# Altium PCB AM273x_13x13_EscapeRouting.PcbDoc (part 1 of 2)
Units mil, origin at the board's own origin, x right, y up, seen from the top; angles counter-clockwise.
Board outline 4950 x 3450 mil, 4 copper layers (Top Layer, GND, Power, Bottom Layer), stack 65.634 mil thick; 41 components, 133 nets, 293 pads, 159 vias.
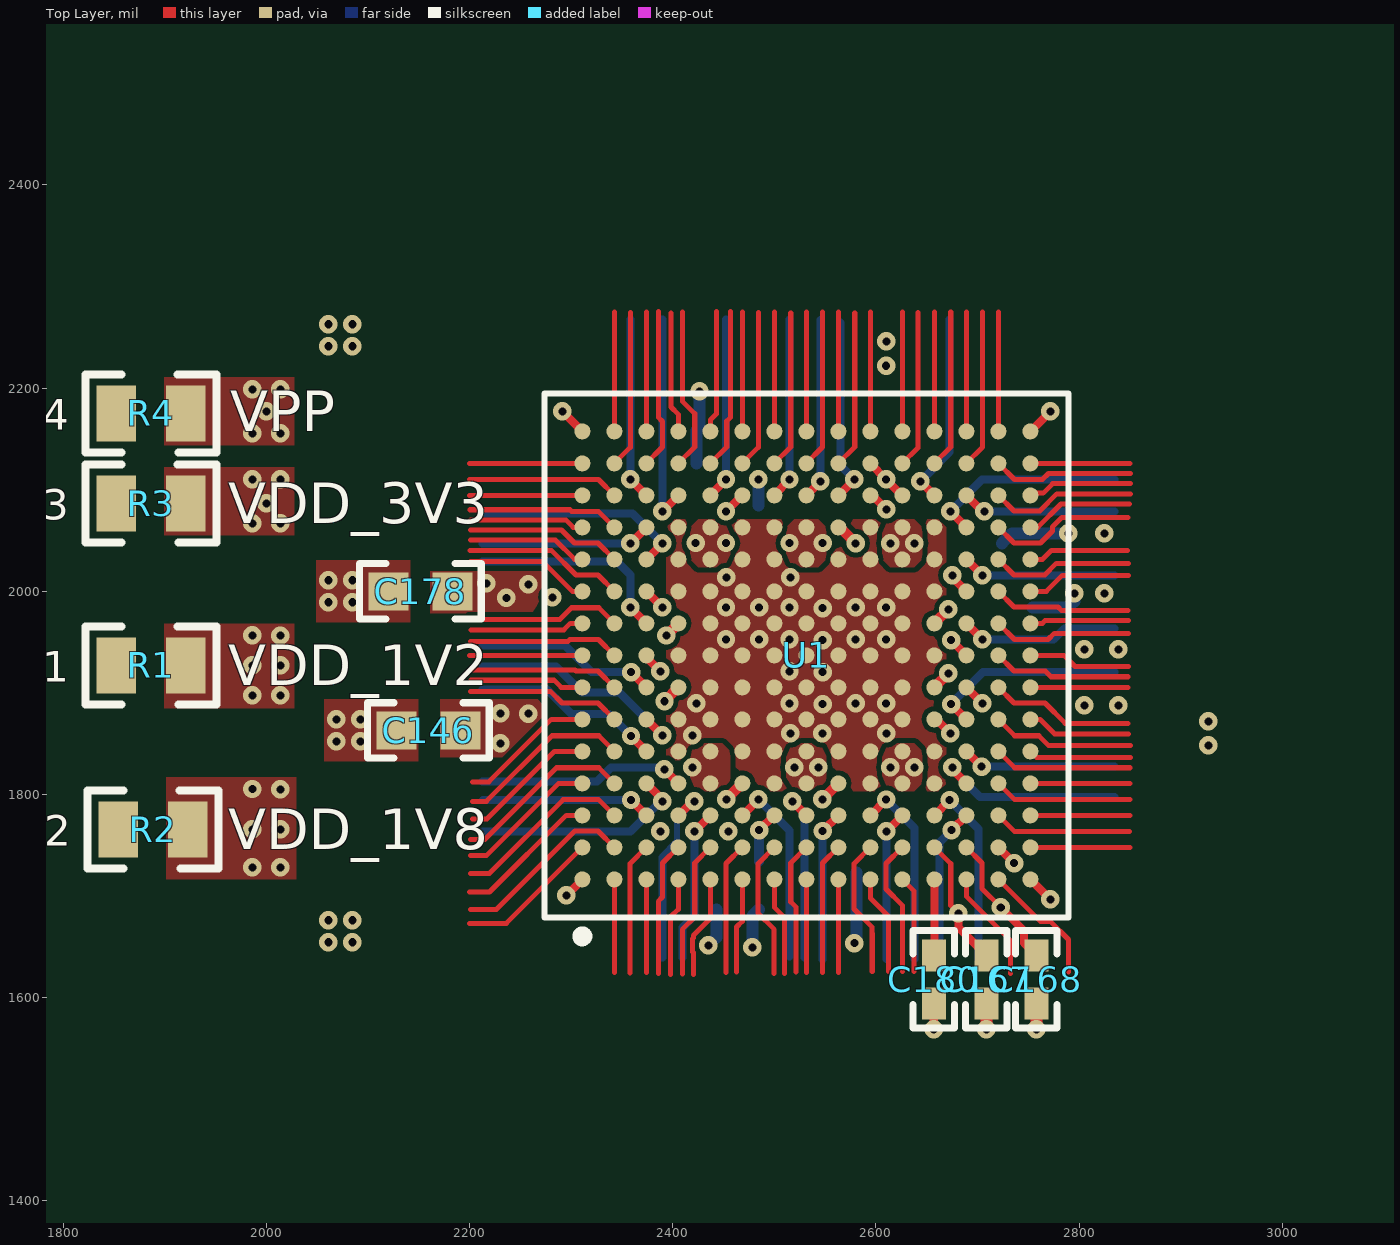
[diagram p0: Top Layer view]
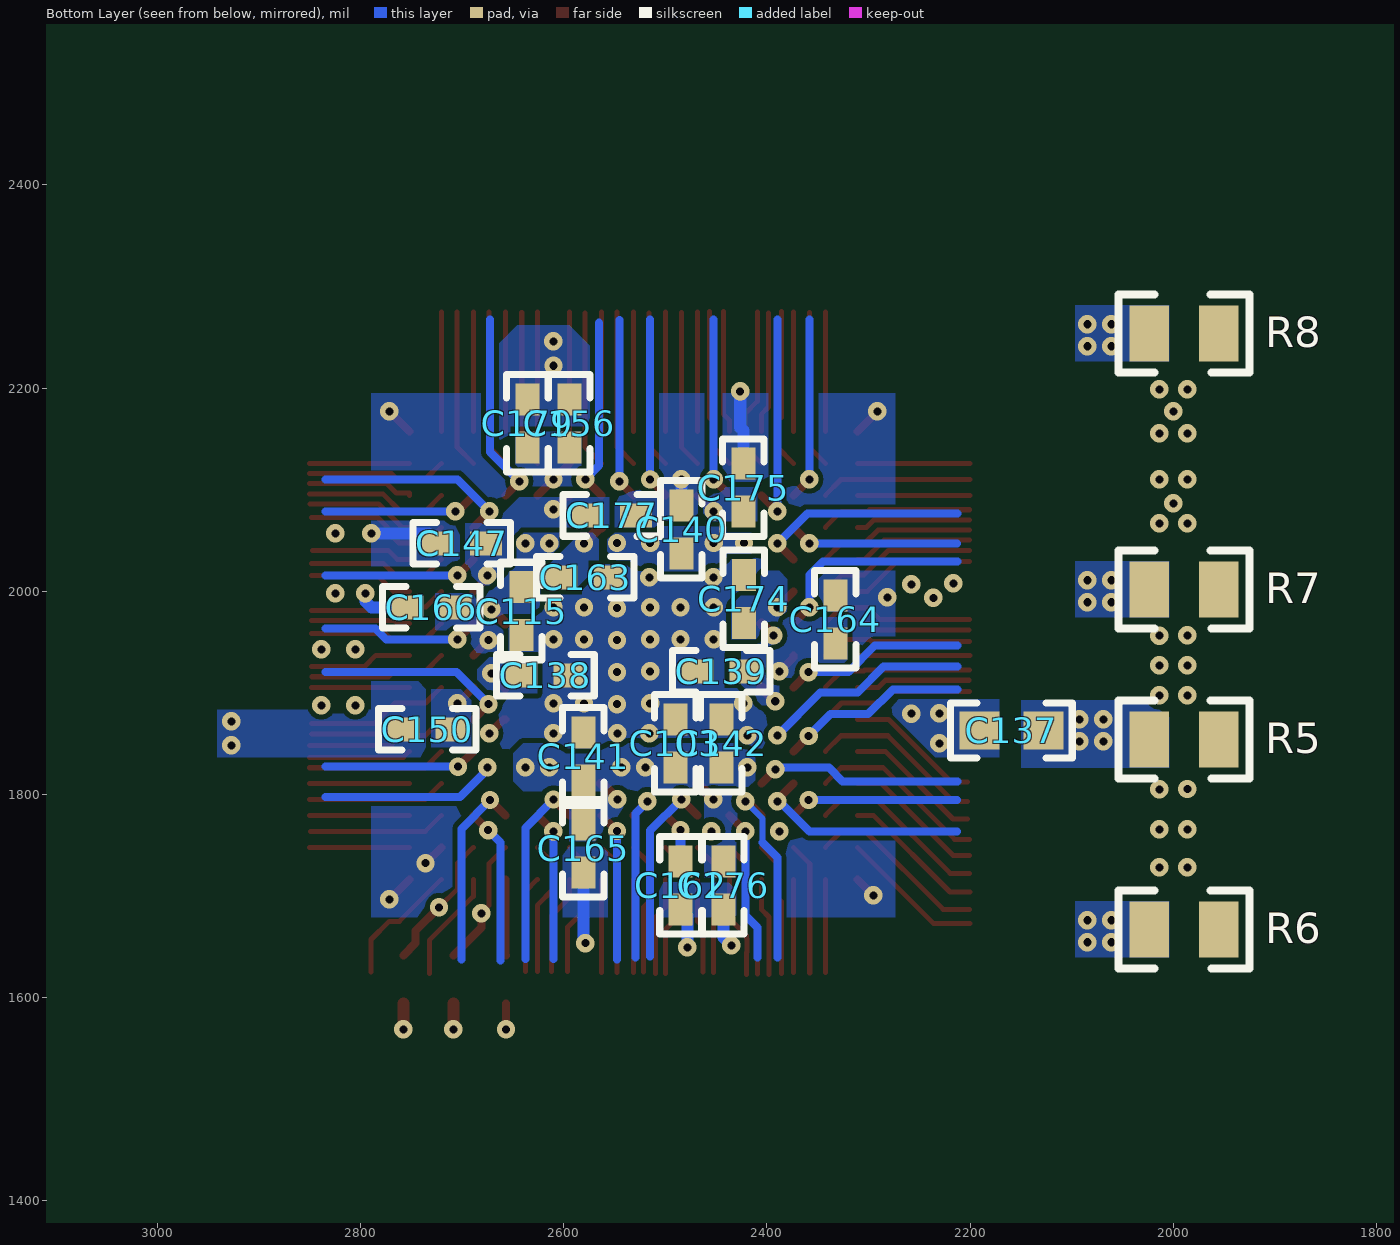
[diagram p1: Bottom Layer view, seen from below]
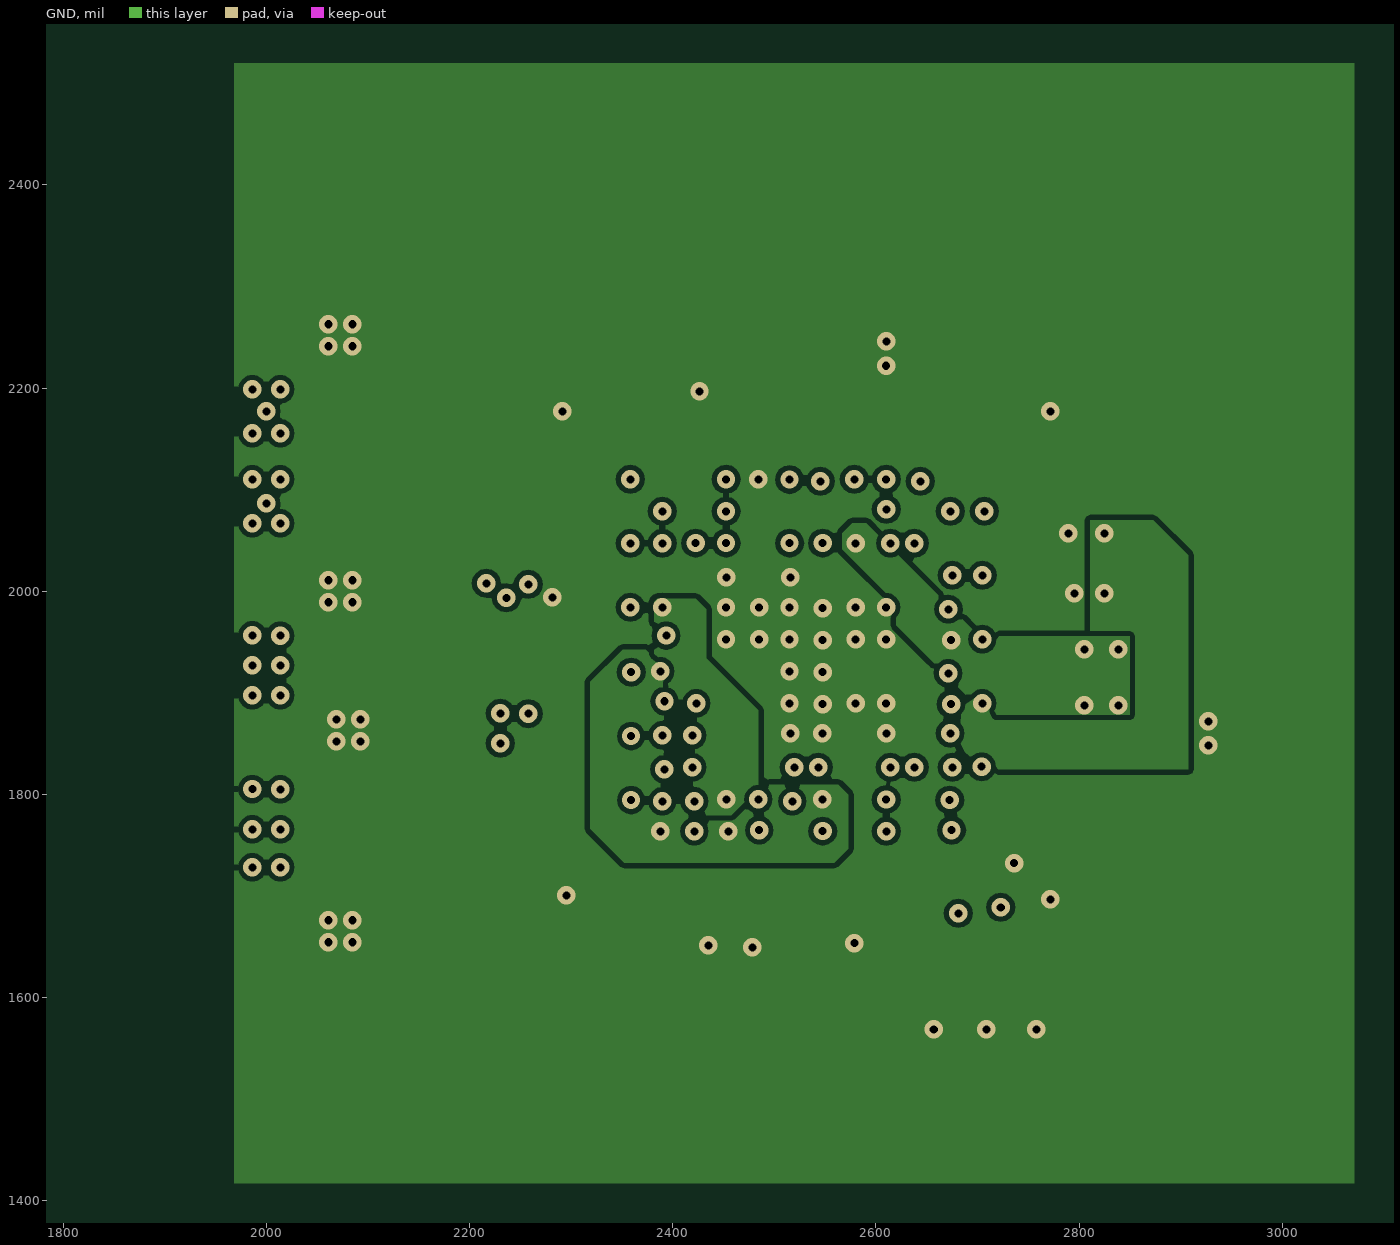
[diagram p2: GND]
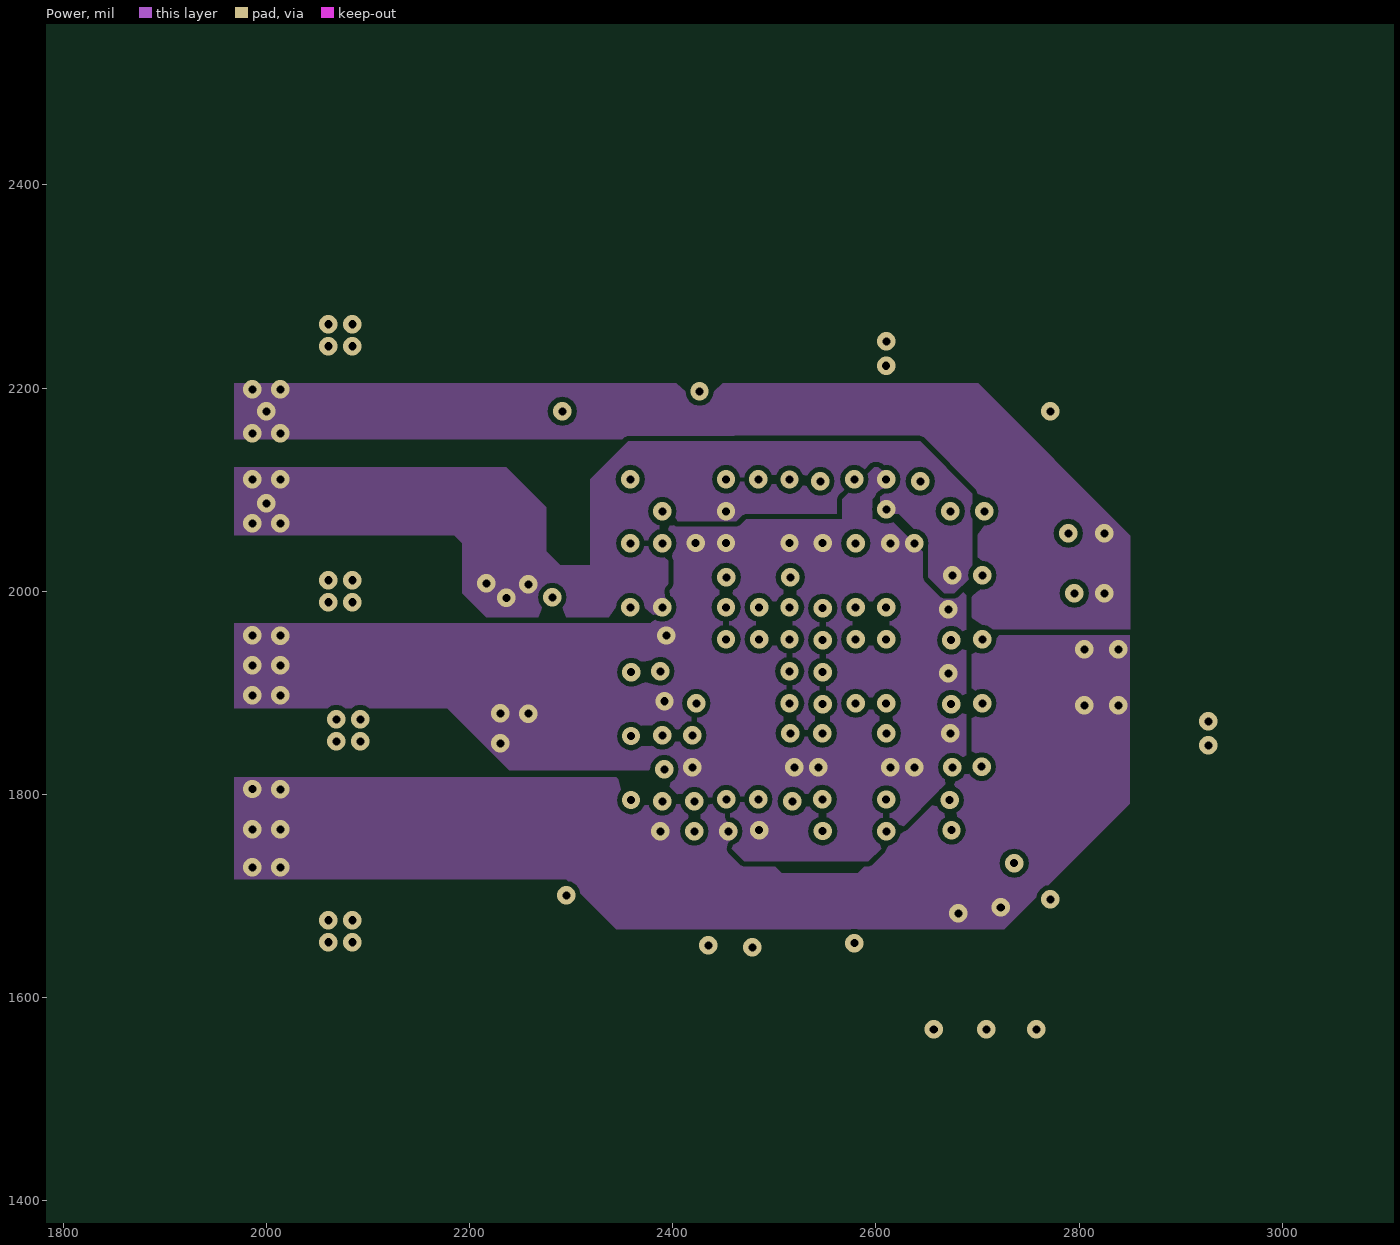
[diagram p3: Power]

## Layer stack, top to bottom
Top Solder: solder mask 0.4, Solder Resist, Dk 3.5
Top Layer: signal copper 1.4
Dielectric 2: core 10, 370HR, Dk 4.2
GND: signal copper 1.417
Dielectric1: prepreg 40, FR-4 High Tg, Dk 4.2
Power: signal copper 1.417
Dielectric 3: core 10, 370HR, Dk 4.2
Bottom Layer: signal copper 1.4
Bottom Solder: solder mask 0.4, Solder Resist, Dk 3.5

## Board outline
0,0 4950,0 4950,3450 0,3450

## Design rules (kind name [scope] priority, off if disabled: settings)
AcuteAngle [All] p1: minimum=4.50000000000000E+0001 checktracksonly=FALSE
AssemblyTestPointUsage [All] p1: valid=2
BoardOutlineClearance BoardOutlineClearance_MountingHoles [OnCopper and InComponentClass('Mounting Holes')] p1: gap=39.37 ignorepadtopadclearanceinfootprint=FALSE
BoardOutlineClearance BoardOutlineClearance_Poly [OnCopper and IsPoly] p2: gap=25 ignorepadtopadclearanceinfootprint=FALSE
BoardOutlineClearance [OnCopper and Not InComponentClass('Logo') and not InComponentClass('FiducialMark') and not InRegion(1000,500,4000,800) and not InPoly] p3: gap=40 ignorepadtopadclearanceinfootprint=FALSE
Clearance Clearance_Keepouts [((IsTrack Or IsArc) And Not InPoly) And IsFree and IsKeepOut vs ((IsTrack Or IsArc) And Not InPoly) And IsFree and IsKeepOut] p1: gap=0 ignorepadtopadclearanceinfootprint=FALSE
Clearance Clearance_Poly [InPolygon] p2: gap=5 ignorepadtopadclearanceinfootprint=TRUE
Clearance Clearance_FiducialMark [IsKeepOut and InComponentClass('FiducialMark') vs IsPad and InComponentClass('FiducialMark')] p3: gap=0 ignorepadtopadclearanceinfootprint=FALSE
Clearance Clearance_Top [OnLayer('Top Layer') vs OnLayer('Top Layer')] p4: gap=5 ignorepadtopadclearanceinfootprint=TRUE
Clearance Clearance_Bottom [OnLayer('Bottom Layer') vs OnLayer('Bottom Layer')] p5: gap=5 ignorepadtopadclearanceinfootprint=TRUE
Clearance [All] p6: gap=4 ignorepadtopadclearanceinfootprint=TRUE
ComponentClearance ComponentClearance_MountingHoles_FiducialMarks [InComponentClass('Mounting Holes') vs InComponentClass('FiducialMark')] p1: gap=50 collisioncheckmode=3 verticalgap=10 showdistances=FALSE
ComponentClearance ComponentClearance_Shunt [InComponentClass('Header') vs InComponentClass('Shunt')] p2: gap=0 collisioncheckmode=3 verticalgap=0 showdistances=FALSE
ComponentClearance ComponentClearance_Logo [InComponentClass('Logo')] p3: gap=30 collisioncheckmode=3 verticalgap=10 showdistances=FALSE
ComponentClearance ComponentClearance_ScrewToNut [(HasFootprint('NY PMS 440 0025 PH')) vs (HasFootprint('Keystone_1902C'))] p4: gap=5 collisioncheckmode=3 verticalgap=10 showdistances=FALSE
ComponentClearance ComponentClearance_MountingHoles [InComponentClass('Mounting Holes')] p5: gap=100 collisioncheckmode=3 verticalgap=100000 showdistances=FALSE
ComponentClearance ComponentClearance_SmallPassives [HasFootprint('0201*') or HasFootprint('0402*') or HasFootprint('0508') or HasFootprint('0603*') or HasFootprint('0612') or HasFootprint('0805*') or HasFootprint('0815*') or HasFootprint('0830*') or HasFootprint('1206*') or HasFootprint('1210*') or HasFootprint('1808*') or HasFootprint('1812*') or HasFootprint('1825*') or HasFootprint('2010*') or HasFootprint('2220*') or HasFootprint('2225*') or HasFootprint('2512*') or HasFootprint('2728*') or HasFootprint('3518*') vs HasFootprint('0201*') or HasFootprint('0402*') or HasFootprint('0508') or HasFootprint('0603*') or HasFootprint('0612') or HasFootprint('0805*') or HasFootprint('0815*') or HasFootprint('0830*') or HasFootprint('1206*') or HasFootprint('1210*') or HasFootprint('1808*') or HasFootprint('1812*') or HasFootprint('1825*') or HasFootprint('2010*') or HasFootprint('2220*') or HasFootprint('2225*') or HasFootprint('2512*') or HasFootprint('2728*') or HasFootprint('3518*')] p6: gap=14.96 collisioncheckmode=3 verticalgap=10 showdistances=FALSE
ComponentClearance ComponentClearance_THtoSMT [IsThruComponent vs IsSMTComponent] p7: gap=30 collisioncheckmode=3 verticalgap=30 showdistances=FALSE
ComponentClearance ComponentClearance_THtoTH [IsThruComponent vs IsThruComponent] p8: gap=20 collisioncheckmode=3 verticalgap=30 showdistances=FALSE
ComponentClearance [All] p9: gap=20 collisioncheckmode=3 verticalgap=10 showdistances=FALSE
DiffPairsRouting [All] p1: maxlimit=100 minlimit=10 mostfreqgap=10 toplayer_minwidth=15 toplayer_maxwidth=15 toplayer_prefwidth=15 midlayer1_minwidth=15 midlayer1_maxwidth=15 midlayer1_prefwidth=15 midlayer2_minwidth=15 midlayer2_maxwidth=15 midlayer2_prefwidth=15 bottomlayer_minwidth=15 bottomlayer_maxwidth=15 bottomlayer_prefwidth=15 maxuncoupledlength=1000
FabricationTestPointUsage TestPointUsage [All] p1: valid=2 allowmultiple=FALSE
FabricationTestpoint Testpoint [All] p1: side=3 testpointundercomponent=TRUE minsize=40 maxsize=100 preferedsize=60 minholesize=0 maxholesize=40 preferedholesize=32 testpointgrid=1 allowsidetop=TRUE allowsidebottom=TRUE usegrid=TRUE gridtolerance=0.01
FanoutControl Fanout_LCC [IsLCC] p1: bgadir=Out bgaviamode=Centered fanoutstyle=Auto fanoutdirection=Alternating viagrid=1 // Fanout_LCC (Default Rule)
FanoutControl Fanout_BGA [IsBGA] p2: bgadir=Out bgaviamode=Centered fanoutstyle=Auto fanoutdirection=Alternating viagrid=1 // Fanout_BGA (Default Rule)
FanoutControl Fanout_Default [All] p4: bgadir=Out bgaviamode=Centered fanoutstyle=Auto fanoutdirection=Alternating viagrid=1 // Fanout_Default (Default Rule)
FanoutControl Fanout_Small [(CompPinCount < 5)] p5: bgadir=Out bgaviamode=Centered fanoutstyle=Auto fanoutdirection=OutThenIn viagrid=1 // Fanout_Small (Default Rule)
HoleSize [All] p1: absolutevalues=TRUE maxlimit=251 minlimit=7.87 maxpercent=80.000 minpercent=20.000
MinimumAnnularRing MinimumAnnularRing_ThermalPadVias [IsVia and InAnyComponent] p1: minimumring=5.91
MinimumAnnularRing [All] p2: minimumring=5
MinimumSolderMaskSliver MinimumSolderMaskSliver_Logo [InComponentClass('Logo') vs InComponentClass('Logo')] p1: minsoldermaskwidth=0.7
MinimumSolderMaskSliver [All] p2: minsoldermaskwidth=3.94
PlaneConnect [All] p1: planeconnectstyle=Relief reliefexpansion=10 reliefentries=4 reliefconductorwidth=10 reliefairgap=10
PolygonConnect [All] p1: connectstyle=Direct reliefconductorwidth=10 reliefentries=4 polygonreliefangle="90 Angle" airgapwidth=10
RoutingVias ThermalPadVias [IsVia and InAnyComponent] p1: holewidth=7.87 width=19.68 viastyle="Through Hole" minholewidth=7.87 minwidth=19.68 maxholewidth=12.99 maxwidth=23.62
RoutingVias [All] p2: holewidth=8 width=18 viastyle="Through Hole" minholewidth=7.87 minwidth=18 maxholewidth=40 maxwidth=65
SilkToBoardRegionClearance [Not ((IsComment or IsDesignator) And (Hide <> 'False')) and not InRegion(1000,500,4000,800)] p1:
SilkToSilkClearance SilkToSilkClearance_Pb-FreeLogo [(HasFootprint('Pb-Free_Overlay_Medium') OR HasFootprint('Pb-Free_Overlay_Small')) vs (HasFootprint('Pb-Free_Overlay_Medium') OR HasFootprint('Pb-Free_Overlay_Small'))] p1: silktosilkclearance=0
SilkToSilkClearance [All] p2: silktosilkclearance=0
SilkToSolderMaskClearance SilkToComponentPadClearance [(IsPad or IsFill or IsRegion) and InAnycomponent] p1: minsilkscreentomaskgap=5 clearancetoexposedcopper=TRUE
SilkToSolderMaskClearance "Silk to Solder Mask Opening" [All] p2: minsilkscreentomaskgap=0 clearancetoexposedcopper=FALSE
SolderMaskExpansion [All] p1: expansion=1.97 istentingtop=FALSE
UnRoutedNet [All] p1: checkbadconnections=TRUE
Width [All] p1: maxlimit=100 minlimit=4 preferedwidth=10 checkconnectedcopper=TRUE
14 further rules are at their usual default settings.

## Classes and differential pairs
component class AM273x_Device: C103 C115 C137 C138 C139 C140 C141 C142 C146 C147 C150 C156 C162 C163 C164 C165 C166 C167 C168 C174 C175 C176 C177 C178 C179 C180 R1 R2 R3 R4 R5 R6 R7 R8 U1
component class Logo: Logo1
component class AM273x_13x13_EscapeRouting_Hardware: Logo1 Logo3 ZZ1 ZZ2 ZZ3 ZZ4
component class AssemblyNote: ZZ1 ZZ2 ZZ3 ZZ4

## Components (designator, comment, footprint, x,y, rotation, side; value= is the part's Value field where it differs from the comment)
C103 "CGA2B3X7R1H103K050BB" 0402 2490.16,1850.39 r270 bottom value=0.01uF
C115 "CGA2B3X7R1H103K050BB" 0402 2641.73,1980.63 r90 bottom value=0.01uF
C137 "GRM188R61C225KAAD" 0603 2159.45,1863.08 r0 bottom value=2.2uF
C138 "GRM155R71A224KE01D" 0402 2618.03,1917.32 r0 bottom value=0.22uF
C139 "GRM155R71A224KE01D" 0402 2444.88,1921.26 r180 bottom value=0.22uF
C140 "GRM155R71A224KE01D" 0402 2484.25,2061.02 r270 bottom value=0.22uF
C141 "GRM155R71A224KE01D" 0402 2580.71,1837.5 r270 bottom value=0.22uF
C142 "GRM155R71A224KE01D" 0402 2444.88,1850.39 r270 bottom value=0.22uF
C146 "GRM188R61C225KAAD" 0603 2159.45,1863.08 r0 top value=2.2uF
C147 "GRM155R71A224KE01D" 0402 2700.29,2047.24 r180 bottom value=0.22uF
C150 "GCM155R71C104KA55D" 0402 2734.25,1864.17 r180 bottom value=0.1uF
C156 "GRM155R71A224KE01D" 0402 2594.49,2165.35 r270 bottom value=0.22uF
C162 "GCM155R71C104KA55D" 0402 2485,1710.63 r90 bottom value=0.1uF
C163 "GRM155R71A224KE01D" 0402 2578.74,2013.78 r0 bottom value=0.22uF
C164 "GRM155R71A224KE01D" 0402 2332.68,1972.44 r270 bottom value=0.22uF
C165 "GRM155R71A224KE01D" 0402 2580.71,1746.98 r90 bottom value=0.22uF
C166 "GRM155R71A224KE01D" 0402 2730.32,1984.25 r180 bottom value=0.22uF
C167 "GRM155R71A224KE01D" 0402 2708.66,1618.11 r90 top value=0.22uF
C168 "GRM155R71A224KE01D" 0402 2757.87,1618.11 r90 top value=0.22uF
C174 "GRM155R71A224KE01D" 0402 2422.74,1992.62 r270 bottom value=0.22uF
C175 "GRM155R71A224KE01D" 0402 2423.23,2102.15 r270 bottom value=0.22uF
C176 "GRM155R71A224KE01D" 0402 2442.91,1710.63 r90 bottom value=0.22uF
C177 "GRM155R71A224KE01D" 0402 2552.7,2074.69 r0 bottom value=0.22uF
C178 "GRM188R61C225KAAD" 0603 2151.57,2000 r0 top value=2.2uF
C179 "GCM155R71C104KA55D" 0402 2635.83,2165.35 r270 bottom value=0.1uF
C180 "CGA2B3X7R1H473K050BB" 0402 2656.89,1618.11 r90 top value=0.047uF
Logo1 "Texas Instruments" TI_Stacked_Overlay_Small 3240,140 r0 top
Logo3 "FCC disclaimer" FCC_disclaimer 2350,3380 r0 top
R1 "5106" 5106 1885.83,1927.17 r0 top value=0
R2 "5106" 5106 1887.8,1765.75 r0 top value=0
R3 "5106" 5106 1885.83,2086.61 r0 top value=0
R4 "5106" 5106 1885.83,2175.2 r0 top value=0
R5 "5106" 5106 1990.16,1854.33 r180 bottom value=0
R6 "5106" 5106 1990.16,1667.32 r180 bottom value=0
R7 "5106" 5106 1990.16,2001.97 r180 bottom value=0
R8 "5106" 5106 1990.16,2253.94 r180 bottom value=0
U1 "AM2732ADRFGQNZNRQ1" NZN0225A-MFG 2531.5,1937.01 r90 top
ZZ1 "This Assembly Note is for PCB labels only" AssemblyNoteLabel 185,3938 r0 top
ZZ2 "These assemblies are ESD sensitive, ESD precautions shall be observed." AssemblyNote 185,3829.11 r0 top
ZZ3 "These assemblies must be clean and free from flux and all contaminants. Use of no clean flux is not acceptable." AssemblyNote 185,3740.56 r0 top
ZZ4 "These assemblies must comply with workmanship standards IPC-A-610 Class 2, unless otherwise specified." AssemblyNote 185,3652 r0 top

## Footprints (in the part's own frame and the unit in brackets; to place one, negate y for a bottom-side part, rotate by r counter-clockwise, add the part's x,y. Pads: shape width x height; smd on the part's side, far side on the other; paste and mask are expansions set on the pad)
0402 [mm] "0402 from SM-752 data"
  rect 0.8x0.6 smd: 1(-0.6,0) 2(0.6,0)
  silkscreen extent -1.22,-0.52 1.22,0.52, body extent -0.55,-0.3 0.55,0.3, height 0.6
0603 [mm] "0603 from SM-752 data"
  rect 1x0.95 smd: 1(-0.8,0) 2(0.8,0)
  silkscreen extent -1.52,-0.69 1.52,0.69, body extent -0.87,-0.47 0.87,0.47, height 1
5106 [mm] "Keystone"
  rect 0.99x1.4 smd: 1(-0.85,0) 2(0.88,0)
  silkscreen extent -1.63,-0.97 1.65,0.97, body extent -1.06,-0.69 1.06,0.69, height 0.84
AssemblyNote [mil] "Assembly Note"
AssemblyNoteLabel [mil] "Assembly Note for PCB Labels"
FCC_disclaimer [mil]
NZN0225A-MFG [mm]
  round 0.4 smd paste+0 mask-1000: A1(-5.6,5.6) A2(-4.8,5.6) A3(-4,5.6) A4(-3.2,5.6) A5(-2.4,5.6) A6(-1.6,5.6) A7(-0.8,5.6) A8(0,5.6) A9(0.8,5.6) A10(1.6,5.6) A11(2.4,5.6) A12(3.2,5.6) A13(4,5.6) A14(4.8,5.6) A15(5.6,5.6) B1(-5.6,4.8) B2(-4.8,4.8) B3(-4,4.8) B4(-3.2,4.8) B5(-2.4,4.8) B6(-1.6,4.8) B7(-0.8,4.8) B8(0,4.8) B9(0.8,4.8) B10(1.6,4.8) B11(2.4,4.8) B12(3.2,4.8) B13(4,4.8) B14(4.8,4.8) B15(5.6,4.8) C1(-5.6,4) C2(-4.8,4) C3(-4,4) C4(-3.2,4) C5(-2.4,4) C6(-1.6,4) C7(-0.8,4) C8(0,4) C9(0.8,4) C10(1.6,4) C11(2.4,4) C12(3.2,4) C13(4,4) C14(4.8,4) C15(5.6,4) D1(-5.6,3.2) D2(-4.8,3.2) D3(-4,3.2) D4(-3.2,3.2) D5(-2.4,3.2) D6(-1.6,3.2) D7(-0.8,3.2) D8(0,3.2) D9(0.8,3.2) D10(1.6,3.2) D11(2.4,3.2) D12(3.2,3.2) D13(4,3.2) D14(4.8,3.2) D15(5.6,3.2) E1(-5.6,2.4) E2(-4.8,2.4) E3(-4,2.4) E4(-3.2,2.4) E5(-2.4,2.4) E6(-1.6,2.4) E7(-0.8,2.4) E8(0,2.4) E9(0.8,2.4) E10(1.6,2.4) E11(2.4,2.4) E12(3.2,2.4) E13(4,2.4) E14(4.8,2.4) E15(5.6,2.4) F1(-5.6,1.6) F2(-4.8,1.6) F3(-4,1.6) F4(-3.2,1.6) F5(-2.4,1.6) F6(-1.6,1.6) F7(-0.8,1.6) F8(0,1.6) F9(0.8,1.6) F10(1.6,1.6) F11(2.4,1.6) F12(3.2,1.6) F13(4,1.6) F14(4.8,1.6) F15(5.6,1.6) G1(-5.6,0.8) G2(-4.8,0.8) G3(-4,0.8) G4(-3.2,0.8) G5(-2.4,0.8) G6(-1.6,0.8) G7(-0.8,0.8) G8(0,0.8) G9(0.8,0.8) G10(1.6,0.8) G11(2.4,0.8) G12(3.2,0.8) G13(4,0.8) G14(4.8,0.8) G15(5.6,0.8) H1(-5.6,0) H2(-4.8,0) H3(-4,0) H4(-3.2,0) H5(-2.4,0) H6(-1.6,0) H7(-0.8,0) H8(0,0) H9(0.8,0) H10(1.6,0) H11(2.4,0) H12(3.2,0) H13(4,0) H14(4.8,0) H15(5.6,0) J1(-5.6,-0.8) J2(-4.8,-0.8) J3(-4,-0.8) J4(-3.2,-0.8) J5(-2.4,-0.8) J6(-1.6,-0.8) J7(-0.8,-0.8) J8(0,-0.8) J9(0.8,-0.8) J10(1.6,-0.8) J11(2.4,-0.8) J12(3.2,-0.8) J13(4,-0.8) J14(4.8,-0.8) J15(5.6,-0.8) K1(-5.6,-1.6) K2(-4.8,-1.6) K3(-4,-1.6) K4(-3.2,-1.6) K5(-2.4,-1.6) K6(-1.6,-1.6) K7(-0.8,-1.6) K8(0,-1.6) K9(0.8,-1.6) K10(1.6,-1.6) K11(2.4,-1.6) K12(3.2,-1.6) K13(4,-1.6) K14(4.8,-1.6) K15(5.6,-1.6) L1(-5.6,-2.4) L2(-4.8,-2.4) L3(-4,-2.4) L4(-3.2,-2.4) L5(-2.4,-2.4) L6(-1.6,-2.4) L7(-0.8,-2.4) L8(0,-2.4) L9(0.8,-2.4) L10(1.6,-2.4) L11(2.4,-2.4) L12(3.2,-2.4) L13(4,-2.4) L14(4.8,-2.4) L15(5.6,-2.4) M1(-5.6,-3.2) M2(-4.8,-3.2) M3(-4,-3.2) M4(-3.2,-3.2) M5(-2.4,-3.2) M6(-1.6,-3.2) M7(-0.8,-3.2) M8(0,-3.2) M9(0.8,-3.2) M10(1.6,-3.2) M11(2.4,-3.2) M12(3.2,-3.2) M13(4,-3.2) M14(4.8,-3.2) M15(5.6,-3.2) N1(-5.6,-4) N2(-4.8,-4) N3(-4,-4) N4(-3.2,-4) N5(-2.4,-4) N6(-1.6,-4) N7(-0.8,-4) N8(0,-4) N9(0.8,-4) N10(1.6,-4) N11(2.4,-4) N12(3.2,-4) N13(4,-4) N14(4.8,-4) N15(5.6,-4) P1(-5.6,-4.8) P2(-4.8,-4.8) P3(-4,-4.8) P4(-3.2,-4.8) P5(-2.4,-4.8) P6(-1.6,-4.8) P7(-0.8,-4.8) P8(0,-4.8) P9(0.8,-4.8) P10(1.6,-4.8) P11(2.4,-4.8) P12(3.2,-4.8) P13(4,-4.8) P14(4.8,-4.8) P15(5.6,-4.8) R1(-5.6,-5.6) R2(-4.8,-5.6) R3(-4,-5.6) R4(-3.2,-5.6) R5(-2.4,-5.6) R6(-1.6,-5.6) R7(-0.8,-5.6) R8(0,-5.6) R9(0.8,-5.6) R10(1.6,-5.6) R11(2.4,-5.6) R12(3.2,-5.6) R13(4,-5.6) R14(4.8,-5.6) R15(5.6,-5.6)
  silkscreen extent -7.15,-6.55 6.55,6.55, body extent -7.05,-7.05 7.05,7.05, height 0.25
TI_Stacked_Overlay_Small [mil]
  silkscreen extent -418,-98 418,98

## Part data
C103 C115: library part CMP-0006324-2, "CAP, CERM, 0.01 uF, 50 V, +/- 10%, X7R, AEC-Q200 Grade 1, 0402", Cap_Case=0402, Manufacturer=TDK, Supplier Part Number 1=445-6893-1-ND, TempCo=X7R, Tolerance_%=10%, Value1="0.333065 ohm", Value2=50V, ValueDisplayed=0.01uF
C137 C146 C178: library part CMP-0007338-4, "CAP, CERM, 2.2 uF, 16 V, +/- 10%, X5R, 0603", Cap_Case=0603, Manufacturer=MuRata, TempCo=X5R, Tolerance_%=10%, Value1=Unknown, Value2=16V, ValueDisplayed=2.2uF
C138 C139 C140 C141 C142 C147 C156 C163 C164 C165 C166 C167 C168 C174 C175 C176 C177: library part CMP-0006630-1, "CAP, CERM, 0.22 uF, 10 V, +/- 10%, X7R, 0402", Cap_Case=0402, Manufacturer=MuRata, Supplier Part Number 1=490-12706-1-ND, TempCo=X7R, Tolerance_%=10%, Value1=Unknown, Value2=10V, ValueDisplayed=0.22uF
C150 C162 C179: library part CMP-0006351-2, "CAP, CERM, 0.1 uF, 16 V, +/- 10%, X7R, 0402", Cap_Case=0402, Manufacturer=MuRata, Supplier Part Number 1=490-4759-2-ND, TempCo=X7R, Tolerance_%=10%, Value1=Unknown, Value2=16V, ValueDisplayed=0.1uF
C180: library part CMP-0006330-2, "CAP, CERM, 0.047 uF, 50 V, +/- 10%, X7R, AEC-Q200 Grade 1, 0402", Cap_Case=0402, Manufacturer=TDK, Supplier Part Number 1=445-6897-1-ND, TempCo=X7R, Tolerance_%=10%, Value1="0.06407 ohm", Value2=50V, ValueDisplayed=0.047uF
Logo1: library part CMP-0074838-1, "Texas Instrument Corporate Signature"
Logo3: library part CMP-0074847-1, "FCC_disclaimer"
R1 R2 R3 R4 R5 R6 R7 R8: library part CMP-0020833-2, "RES, 0, 1%, 0.5 W, 0805", Manufacturer=Keystone, Power_W=500mW, Supplier Part Number 1=36-5106CT-ND, TempCo=ppm/C, Tolerance_%=1%, Value2=0.5W, Value_Code=0
U1: library part CMP-0093973-1, "TPR12", Manufacturer="Texas Instruments", Operating Temperature Range=to
ZZ1: library part CMP-0003616-3
ZZ2: library part CMP-0077236-1
ZZ3: library part CMP-0077237-1
ZZ4: library part CMP-0077238-1

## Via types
v1: diameter 18, hole 8, Top Layer to Bottom Layer, tented both sides, 135 vias
v2: diameter 18, hole 8, Top Layer to Bottom Layer, 24 vias

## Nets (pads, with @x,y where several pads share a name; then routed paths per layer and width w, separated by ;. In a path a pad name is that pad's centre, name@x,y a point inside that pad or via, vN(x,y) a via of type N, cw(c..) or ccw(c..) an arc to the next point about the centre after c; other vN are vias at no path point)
A2: U1.A2 | length 142
  Top Layer w5: 2200,1673.23 2236.22,1673.23 U1.A2@2311.02,1748.03
A3: U1.A3 | length 142.3
  Top Layer w5: 2200,1703.98 2219.72,1703.98 2295.28,1779.53 U1.A3@2311.02,1779.53
A4: U1.A4 | length 139.6
  Top Layer w5: 2200.79,1740.16 2216.82,1740.16 2287.69,1811.02 U1.A4@2311.02,1811.02
A5: U1.A5 | length 135.9
  Top Layer w5: 2202.76,1775.91 2216.96,1775.91 2283.57,1842.52 U1.A5@2311.02,1842.52
A6: U1.A6 | length 133.7
  Top Layer w5: 2202.76,1812.5 2218.96,1812.5 2280.48,1874.02 U1.A6@2311.02,1874.02
A7: U1.A7 | length 112.6
  Top Layer w5: 2201.3,1912.5 2283.24,1912.5 2290.23,1905.51 U1.A7@2311.02,1905.51
A8: U1.A8 | length 111
  Top Layer w5: 2200,1937.01 U1.A8@2311.02,1937.01
A9: U1.A9 | length 112.4
  Top Layer w5: 2201.3,1962.08 2292.79,1962.08 2299.21,1968.5 U1.A9@2311.02,1968.5
A10: U1.A10 | length 122.5
  Top Layer w5: 2200.79,2029.53 2271.65,2029.53 2301.18,2000 U1.A10@2311.02,2000
A11: U1.A11 | length 118
  Top Layer w5: 2200.79,2050.35 2284.57,2050.35 2303.42,2031.5 U1.A11@2311.02,2031.5
A12: U1.A12 | length 113.3
  Top Layer w5: 2200.79,2070.35 2294.67,2070.35 2302.04,2062.99 U1.A12@2311.02,2062.99
A13: U1.A13 | length 111
  Top Layer w5: 2200,2094.49 U1.A13@2311.02,2094.49
A14: U1.A14 | length 111
  Top Layer w5: 2200,2125.98 U1.A14@2311.02,2125.98
B1: U1.B1 | length 91.5
  Top Layer w5: 2342.52,1625 U1.B1@2342.52,1716.54
B2: U1.B2 | length 180.4
  Top Layer w5: 2200.79,1687.01 2226.48,1687.01 2303.63,1764.15 2326.4,1764.15 U1.B2@2342.52,1748.03
B3: U1.B3 | length 178.2
  Top Layer w5: 2200.79,1722.44 2219.55,1722.44 2292.11,1795 2327.05,1795 U1.B3@2342.52,1779.53
B4: U1.B4 | length 177.3
  Top Layer w5: 2200.79,1755.91 2215.17,1755.91 2285.66,1826.4 2327.15,1826.4 U1.B4@2342.52,1811.02
B5: U1.B5 | length 172.9
  Top Layer w5: 2202.76,1793.31 2216.54,1793.31 2281.12,1857.89 2327.15,1857.89 U1.B5@2342.52,1842.52
B6: U1.B6 | length 153.1
  Top Layer w5: 2200.79,1901.57 2279.53,1901.57 2291.1,1890 2326.54,1890 U1.B6@2342.52,1874.02
B7: U1.B7 | length 149.1
  Top Layer w5: 2200.47,1922.5 2303.79,1922.5 2304.66,1921.63 2326.4,1921.63 U1.B7@2342.52,1905.51
B8: U1.B8 | length 148.9
  Top Layer w5: 2200.79,1950.79 2297.04,1950.79 2298.75,1952.5 2327.03,1952.5 U1.B8@2342.52,1937.01
B9: U1.B9 | length 152.8
  Top Layer w5: 2200.79,1972.44 2288.93,1972.44 2300.36,1983.88 2327.15,1983.88 U1.B9@2342.52,1968.5
B10: U1.B10 | length 158.8
  Top Layer w5: 2200.47,2040.35 2280.42,2040.35 2304.66,2016.12 2326.4,2016.12 U1.B10@2342.52,2000
B11: U1.B11 | length 153.7
  Top Layer w5: 2200.79,2060.35 2290.53,2060.35 2303.39,2047.5 2326.52,2047.5 U1.B11@2342.52,2031.5
B12: U1.B12 | length 149.2
  Top Layer w5: 2200.47,2080.35 2298.82,2080.35 2300.43,2078.74 2326.77,2078.74 U1.B12@2342.52,2062.99
B13: U1.B13 | length 148.9
  Top Layer w5: 2200,2110 2327.01,2110 U1.B13@2342.52,2094.49
B14: U1.B14 | length 154.8
  Top Layer w5: U1.B14@2342.52,2125.98 2358.27,2141.73 2358.27,2274.23
B15: U1.B15 | length 117.5
  Top Layer w5: U1.B15@2342.52,2157.48 2342.52,2274.98
C1: U1.C1 | length 91.5
  Top Layer w5: 2374.02,1625 U1.C1@2374.02,1716.54
C2: U1.C2 | length 130.3
  Top Layer w5: 2357.89,1624.41 2357.89,1731.91 U1.C2@2374.02,1748.03
C3: U1.C3 | length 167.2
  Top Layer w8: v1(2359,1794.55) U1.C3@2374.02,1779.53
  Bottom Layer w8: 2213.05,1794.55 v1(2359,1794.55)
C4: U1.C4 | length 213.2
  Top Layer w8: U1.C4@2374.02,1811.02 2389.76,1795.28 v1(2389.76,1793.31)
  Bottom Layer w8: 2213.05,1763.78 2358.27,1763.78 2387.8,1793.31 v1(2389.76,1793.31)
C5: U1.C5 | length 186.7
  Top Layer w8: v1(2359,1857.54) U1.C5@2374.02,1842.52
  Bottom Layer w8: 2212.6,1903.54 2276.12,1903.54 2300.49,1879.17 2337.37,1879.17 v1(2359,1857.54)
C6: U1.C6 | length 227.5
  Top Layer w8: U1.C6@2374.02,1874.02 v1(2389.76,1858.27)
  Bottom Layer w8: 2212.6,1925.95 2285.18,1925.95 2310.65,1900.49 2347.54,1900.49 v1(2389.76,1858.27)
C7: U1.C7 | length 178.4
  Top Layer w8: v1(2359.04,1920.49) U1.C7@2374.02,1905.51
  Bottom Layer w8: 2212.64,1946.53 2293.88,1946.53 2319.91,1920.49 v1(2359.04,1920.49)
C9: U1.C9 | length 207.4
  Top Layer w8: v1(2358.27,1984.25) U1.C9@2374.02,1968.5
  Bottom Layer w6: v1@2356.3,1984.25 v1(2358.27,1984.25)
  Bottom Layer w8: 2212.6,2029.53 2344.98,2029.53 2358.27,2016.24 v1(2358.27,1984.25)
C11: U1.C11 | length 211.6
  Top Layer w8: U1.C11@2374.02,2031.5 v1(2389.76,2047.24)
  Bottom Layer w8: 2212.64,2076.77 2360.24,2076.77 v1(2389.76,2047.24)
C12: U1.C12 | length 167.7
  Top Layer w8: v1(2358.27,2047.24) U1.C12@2374.02,2062.99
  Bottom Layer w8: 2212.85,2047.24 v1(2358.27,2047.24)
C13: U1.C13 | length 179.8
  Top Layer w8: v1(2358.27,2110.24) U1.C13@2374.02,2094.49
  Bottom Layer w8: v1(2358.27,2110.24) 2358.27,2267.72
C14: U1.C14 | length 158
  Top Layer w5: U1.C14@2374.02,2125.98 2390,2141.97 2390,2167.09 2385.83,2171.26 2385.83,2275.59
C15: U1.C15 | length 117.5
  Top Layer w5: U1.C15@2374.02,2157.48 2374.02,2274.98
D1: U1.D1 | length 96.6
  Top Layer w5: 2397.89,1623.05 2397.89,1679.38 2405.51,1687.01 U1.D1@2405.51,1716.54
D2: U1.D2 | length 132.2
  Top Layer w5: 2385.83,1624.02 2385.83,1694.88 2390,1699.06 2390,1732.52 U1.D2@2405.51,1748.03
D3: U1.D3 | length 188
  Top Layer w8: U1.D3@2405.51,1779.53 2419.29,1793.31 v1(2421.26,1793.31)
  Bottom Layer w6: 2404.3,1752.72 2404.3,1776.34 v1(2421.26,1793.31)
  Bottom Layer w8: 2389.76,1639.76 2389.76,1738.19 2404.3,1752.72
D4: U1.D4 | length 204.9
  Top Layer w8: v1@2390,1826.54 U1.D4@2405.51,1811.02
  Bottom Layer w8: 2212.6,1812.99 2325.51,1812.99 2339.05,1826.54 v1@2390,1826.54
  other v1: 2391.73,1824.8
D13: U1.D13 | length 211
  Top Layer w8: v1(2389.76,2078.74) U1.D13@2405.51,2094.49
  Bottom Layer w8: v1(2389.76,2078.74) 2389.76,2267.48
D14: U1.D14 | length 160.7
  Top Layer w5: U1.D14@2405.51,2125.98 2421.63,2142.11 2421.63,2174.82 2409.45,2187.01 2409.45,2274.98
D15: U1.D15 | length 119.2
  Top Layer w5: 2398.37,2273.75 2398.37,2181.35 2405.51,2174.21 U1.D15@2405.51,2157.48
E1: U1.E1 | length 101
  Top Layer w5: 2420.25,1623.05 2420.25,1644.44 2419.54,1645.15 2419.54,1658 2420.25,1658.71 2420.25,1661.23 2437.01,1677.98 U1.E1@2437.01,1716.54
E2: U1.E2 | length 136.3
  Top Layer w5: 2409.45,1623.19 2409.45,1667.32 2421.63,1679.51 2421.63,1732.66 U1.E2@2437.01,1748.03
E3: U1.E3 | length 151.2
  Top Layer w8: v1(2421.26,1763.78) U1.E3@2437.01,1779.53
  Bottom Layer w8: 2409.45,1639.76 2409.45,1669.29 2421.26,1681.1 v1(2421.26,1763.78)
E13: U1.E13 | length 179.6
  Top Layer w8: U1.E13@2437.01,2094.49 2437.01,2094.74 v1(2452.5,2110.24)
  Bottom Layer w8: v1(2452.5,2110.24) 2452.5,2267.72
E14: U1.E14 | length 157.8
  Top Layer w5: U1.E14@2437.01,2125.98 2453.13,2142.11 2453.13,2167.41 2456.69,2170.97 2456.69,2275.59
E15: U1.E15 | length 120.6
  Top Layer w5: U1.E15@2437.01,2157.48 2437.01,2168.65 2442.91,2174.56 2442.91,2275.59
F1: U1.F1 | length 93.6
  Top Layer w5: 2462.85,1625.25 2462.85,1669.56 2468.5,1675.22 U1.F1@2468.5,1716.54
F2: U1.F2 | length 129.7
  Top Layer w5: 2452.5,1625 2452.5,1732.03 U1.F2@2468.5,1748.03
F3: U1.F3 | length 189.8
  Top Layer w8: U1.F3@2468.5,1779.53 v1(2484.25,1795.27)
  Bottom Layer w8: v1(2484.25,1795.27) 2515,1764.52 2515,1640.51
F14: U1.F14 | length 155.2
  Top Layer w5: U1.F14@2468.5,2125.98 2484.25,2141.73 2484.25,2274.63
F15: U1.F15 | length 117.5
  Top Layer w5: U1.F15@2468.5,2157.48 2468.5,2275
G1: U1.G1 | length 96.6
  Top Layer w5: U1.G1@2500,1716.54 2500,1688.98 2509.84,1679.13 2509.84,1624.02
G2: U1.G2 | length 137.3
  Top Layer w5: 2499.84,1624.02 2499.84,1667.32 2483.88,1683.29 2483.88,1731.91 U1.G2@2500,1748.03
G13: U1.G13 | length 179.4
  Top Layer w8: U1.G13@2500,2094.49 2500,2095 v1(2515,2110)
  Bottom Layer w8: v1(2515,2110) 2515,2267.72
G14: U1.G14 | length 154.7
  Top Layer w5: U1.G14@2500,2125.98 2516.12,2142.11 2516.12,2274
G15: U1.G15 | length 117.5
  Top Layer w5: U1.G15@2500,2157.48 2500,2274.98
GND: C103.1 C115.1 C137.1 C138.1 C139.1 C140.1 C141.1 C142.1 C146.1 C147.1 C150.1 C156.1 C162.1 C163.1 C164.1 C165.1 C166.1 C167.1 C168.1 C174.1 C175.1 C176.1 C177.1 C178.1 C179.1 C180.1 R5.1 R6.1 R7.1 R8.1 U1.A1 U1.A15 U1.D5 U1.D6 U1.D8 U1.D10 U1.D11 U1.D12 U1.E6 U1.E7 U1.E8 U1.E9 U1.E10 U1.F5 U1.F6 U1.F7 U1.F8 U1.F9 U1.F10 U1.F11 U1.F12 U1.G4 U1.G5 U1.G6 U1.G7 U1.G8 U1.G9 U1.G10 U1.G11 U1.G12 U1.H6 U1.H7 U1.H8 U1.H9 U1.H10 U1.J5 U1.J6 U1.J7 U1.J8 U1.J9 U1.J10 U1.J11 U1.K4 U1.K5 U1.K6 U1.K7 U1.K8 U1.K9 U1.K10 U1.K11 U1.K12 U1.L6 U1.L7 U1.L8 U1.L9 U1.L10 U1.M4 U1.M5 U1.M8 U1.M10 U1.M11 U1.M12 U1.P2 U1.R1 U1.R15 | length 577.3
  Top Layer w8: v1(2291.34,2177.17) U1.A15@2311.02,2157.48 ; v1(2295.28,1700.79) U1.A1@2311.02,1716.54 ; v1(2656.89,1568.9) C180.1@2656.89,1594.49 ; U1.P2@2720.47,1748.03 v1(2735.98,1732.52) ; U1.R1@2751.97,1716.54 v1(2771.65,1696.85) ; U1.R15@2751.97,2157.48 v1(2771.65,2177.17)
  Top Layer w12: v2(2708.66,1568.9) C167.1@2708.66,1594.49 ; v2(2757.87,1568.9) C168.1@2757.87,1594.49
  Power w8: v1@2767.25,1696.85 v1(2771.65,1696.85)
  Bottom Layer w12: C175.1@2423.23,2125.77 2423.23,2158.28 2426.37,2161.42 v1(2426.37,2196.85) ; v1(2435.04,1651.57) 2442.91,1659.45 C176.1@2442.91,1687.01 ; v1(2478.35,1649.61) 2478.35,1680.35 C162.1@2485,1687.01 ; C140.1@2484.25,2084.65 v1(2484.25,2110.24) ; v1(2578.74,1653.74) 2580.71,1655.71 C165.1@2580.71,1723.36 ; C147.1@2723.92,2047.24 2733.76,2057.09 v1(2789.37,2057.09) ; C166.1@2753.94,1984.25 2789.37,1984.25 2795.28,1990.16 v1(2795.28,1998.03)
  other v1: 2061.02,1654.64 2084.65,1654.64 2061.02,1676.29 2084.65,1676.29 2927.17,1848.43 2068.9,1852.36 2092.52,1852.36 2419.29,1858.27 2515.75,1860.24 2547.24,1860.24 2610.24,1860.24 2927.17,1872.05 2068.9,1874.02 2092.52,1874.02 2547.5,1889 2423.23,1889.76 2515,1889.76 2580,1889.76 2610,1889.76 2547.5,1920.49 2515,1921.26 2547.5,1951.99 2452.5,1952.76 2485,1952.76 2515,1952.76 2580,1952.76 2610,1952.76 2547.5,1983.48 2452.5,1984.25 2485,1984.25 2515,1984.25 2580,1984.25 2610,1984.25 2061.02,1989.28 2084.65,1989.28 2281.5,1994.09 2061.02,2010.94 2084.65,2010.94 2452.76,2013.78 2515.75,2013.78 2610,2222.09 2061.02,2241.25 2084.65,2241.25 2610.24,2246.06 2061.02,2262.91 2084.65,2262.91
H1: U1.H1 | length 91.5
  Top Layer w5: 2531.5,1625 U1.H1@2531.5,1716.54
H2: U1.H2 | length 131.3
  Top Layer w5: 2521.5,1625.29 2521.5,1689.13 2516.12,1694.51 2516.12,1732.66 U1.H2@2531.5,1748.03
H3: U1.H3 | length 177.9
  Top Layer w8: v1(2517.72,1793.31) U1.H3@2531.5,1779.53
  Bottom Layer w8: v1(2517.72,1793.31) 2529.53,1781.5 2529.53,1639.76
H13: U1.H13 | length 181.2
  Top Layer w8: U1.H13@2531.5,2094.49 v1(2545.28,2108.27) v1@2547.24,2110.23
  Bottom Layer w8: v1(2545.28,2108.27) 2545.28,2267.22
H14: U1.H14 | length 155.6
  Top Layer w5: U1.H14@2531.5,2125.98 2547.5,2141.99 2547.5,2274.98
H15: U1.H15 | length 117.5
  Top Layer w5: U1.H15@2531.5,2157.48 2531.5,2274.98
J1: U1.J1 | length 91.5
  Top Layer w5: 2562.99,1625 U1.J1@2562.99,1716.54
J2: U1.J2 | length 129.4
  Top Layer w5: 2547.5,1625 2547.5,1732.54 U1.J2@2562.99,1748.03
J3: U1.J3 | length 148.1
  Top Layer w8: v1(2547.5,1764.04) U1.J3@2562.99,1779.53
  Bottom Layer w8: 2547.5,1637.8 v1(2547.5,1764.04)
J13: U1.J13 | length 182.1
  Top Layer w8: U1.J13@2562.99,2094.49 v1(2578.74,2110.24)
  Bottom Layer w8: 2565.17,2264.41 2565.17,2123.81 v1(2578.74,2110.24)
J14: U1.J14 | length 154.7
  Top Layer w5: U1.J14@2562.99,2125.98 2579.11,2142.11 2579.11,2274
J15: U1.J15 | length 117.5
  Top Layer w5: U1.J15@2562.99,2157.48 2562.99,2274.98
K1: U1.K1 | length 97.9
  Top Layer w5: U1.K1@2594.49,1716.54 2594.49,1698.26 2612.2,1680.54 2612.2,1625.98
K2: U1.K2 | length 136.2
  Top Layer w5: U1.K2@2594.49,1748.03 2578.37,1731.91 2578.37,1687.38 2596.3,1669.45 2596.3,1663.39 ; 2596.37,1625.98 2596.37,1663.39
K3: U1.K3 | length 190.5
  Top Layer w8: U1.K3@2594.49,1779.53 v1(2610,1795.04)
  Bottom Layer w8: v1(2610,1795.04) 2637.8,1767.24 2637.8,1638.03
K15: U1.K15 | length 117.5
  Top Layer w5: U1.K15@2594.49,2157.48 2594.49,2274.98
L1: U1.L1 | length 95.4
  Top Layer w5: U1.L1@2625.98,1716.54 2637.58,1704.94 2637.58,1625.98
L2: U1.L2 | length 135.3
  Top Layer w5: 2625.98,1625.98 2625.98,1690.94 2610,1706.93 2610,1732.05 U1.L2@2625.98,1748.03
L3: U1.L3 | length 148
  Top Layer w8: v1(2610.24,1763.78) U1.L3@2625.98,1779.53
  Bottom Layer w8: 2610.24,1638.03 v1(2610.24,1763.78)
L14: U1.L14 | length 154.8
  Top Layer w5: U1.L14@2625.98,2125.98 2641.36,2141.36 2641.36,2274.45
L15: U1.L15 | length 117.5
  Top Layer w5: U1.L15@2625.98,2157.48 2625.98,2274.98
M3: U1.M3 | length 189.7
  Top Layer w8: U1.M3@2657.48,1779.53 v1(2672.5,1794.55)
  Bottom Layer w8: v1(2672.5,1794.55) 2700.79,1766.26 2700.79,1637.8
M13: U1.M13 | length 190.9
  Top Layer w8: v1(2643.7,2108.27) U1.M13@2657.48,2094.49
  Bottom Layer w8: v1(2643.7,2108.27) 2672.5,2137.07 2672.5,2267.72
M14: U1.M14 | length 155.4
  Top Layer w5: U1.M14@2657.48,2125.98 2673.6,2142.11 2673.6,2274.74
M15: U1.M15 | length 117.5
  Top Layer w5: U1.M15@2657.48,2157.48 2657.48,2274.98
N1: U1.N1 | length 110.5
  Top Layer w5: U1.N1@2688.98,1716.54 2688.98,1699.8 2732.28,1656.49 2732.28,1624.02
N3: U1.N3 | length 154
  Top Layer w8: v1(2674.45,1765) U1.N3@2688.98,1779.53
  Bottom Layer w8: 2662.4,1636.56 2662.4,1752.95 v1(2674.45,1765)
N4: U1.N4 | length 194.1
  Top Layer w8: v1(2675.2,1826.77) 2675.2,1824.8 U1.N4@2688.98,1811.02
  Bottom Layer w8: v1(2675.2,1826.77) 2675.2,1824.8 2702.26,1797.74 2834.65,1797.74
N5: U1.N5 | length 151.9
  Top Layer w8: U1.N5@2688.98,1842.52 v1(2704,1827.5)
  Bottom Layer w8: v1(2704,1827.5) 2834.65,1827.5
N6: U1.N6 | length 194.9
  Top Layer w8: v1(2674,1889) U1.N6@2688.98,1874.02
  Bottom Layer w8: v1(2674,1889) 2705.49,1920.49 2834.65,1920.49
N9: U1.N9 | length 156.6
  Top Layer w8: U1.N9@2688.98,1968.5 v1(2704.72,1952.76)
  Bottom Layer w8: v1(2704.72,1952.76) 2774.71,1952.76 2785.43,1963.48 2834.65,1963.48
N11: U1.N11 | length 152.2
  Top Layer w8: U1.N11@2688.98,2031.5 v1(2704.72,2015.75)
  Bottom Layer w8: v1(2704.72,2015.75) 2834.65,2015.75
N12: U1.N12 | length 196.6
  Top Layer w8: v1(2673.23,2078.74) U1.N12@2688.98,2062.99
  Bottom Layer w8: v1(2673.23,2078.74) 2704.49,2110 2834.65,2110
N13: U1.N13 | length 152.2
  Top Layer w8: U1.N13@2688.98,2094.49 2704.72,2078.74 v1(2706.69,2078.74)
  Bottom Layer w8: v1(2706.69,2078.74) 2834.65,2078.74
N14: U1.N14 | length 155.6
  Top Layer w5: U1.N14@2688.98,2125.98 2705,2142.01 2705,2274.98
N15: U1.N15 | length 117.5
  Top Layer w5: U1.N15@2688.98,2157.48 2688.98,2274.98
P1: U1.P1 | length 125.7
  Top Layer w5: U1.P1@2720.47,1716.54 2761.81,1675.2 2771.65,1675.2 2789.62,1657.23 2789.62,1625.25
P3: U1.P3 | length 135.4
  Top Layer w5: U1.P3@2720.47,1779.53 2736.22,1763.78 2849.3,1763.78
P4: U1.P4 | length 136.2
  Top Layer w5: U1.P4@2720.47,1811.02 2736.5,1795 2850,1795
P5: U1.P5 | length 136.2
  Top Layer w5: U1.P5@2720.47,1842.52 2736.59,1826.4 2850.02,1826.4
P6: U1.P6 | length 140.5
  Top Layer w5: U1.P6@2720.47,1874.02 2736.59,1857.89 2760.22,1857.89 2769.68,1848.43 2850.39,1848.43
P7: U1.P7 | length 142.2
  Top Layer w5: U1.P7@2720.47,1905.51 2735.98,1890 2766.27,1890 2786.19,1870.08 2848.03,1870.08
P8: U1.P8 | length 136.2
  Top Layer w5: U1.P8@2720.47,1937.01 2735.85,1921.63 2766.64,1921.63 2772.32,1915.95 2847.98,1915.95
P9: U1.P9 | length 137.1
  Top Layer w5: U1.P9@2720.47,1968.5 2736.48,1952.5 2769.43,1952.5 2775.59,1958.66 2848.43,1958.66
P10: U1.P10 | length 135.4
  Top Layer w5: U1.P10@2720.47,2000 2735.85,1984.63 2779.15,1984.63 2782.46,1981.32 2848.09,1981.32
P11: U1.P11 | length 139.1
  Top Layer w5: U1.P11@2720.47,2031.5 2735.85,2016.12 2766.12,2016.12 2777.56,2027.56 2848.43,2027.56
P12: U1.P12 | length 147
  Top Layer w5: U1.P12@2720.47,2062.99 2735.96,2047.5 2762.07,2047.5 2773.87,2059.3 2773.87,2063.51 2782.95,2072.59 2848.18,2072.59
P13: U1.P13 | length 143.3
  Top Layer w5: U1.P13@2720.47,2094.49 2735.85,2079.11 2761.19,2079.11 2778.06,2095.98 2850.39,2095.98
P14: U1.P14 | length 139
  Top Layer w5: U1.P14@2720.47,2125.98 2736.46,2110 2763.79,2110 2769.78,2115.98 2850.39,2115.98
P15: U1.P15 | length 117.5
  Top Layer w5: U1.P15@2720.47,2157.48 2720.47,2274.98
R2: U1.R2 | length 98
  Top Layer w5: U1.R2@2751.97,1748.03 2850,1748.03
R3: U1.R3 | length 98
  Top Layer w5: U1.R3@2751.97,1779.53 2850,1779.53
